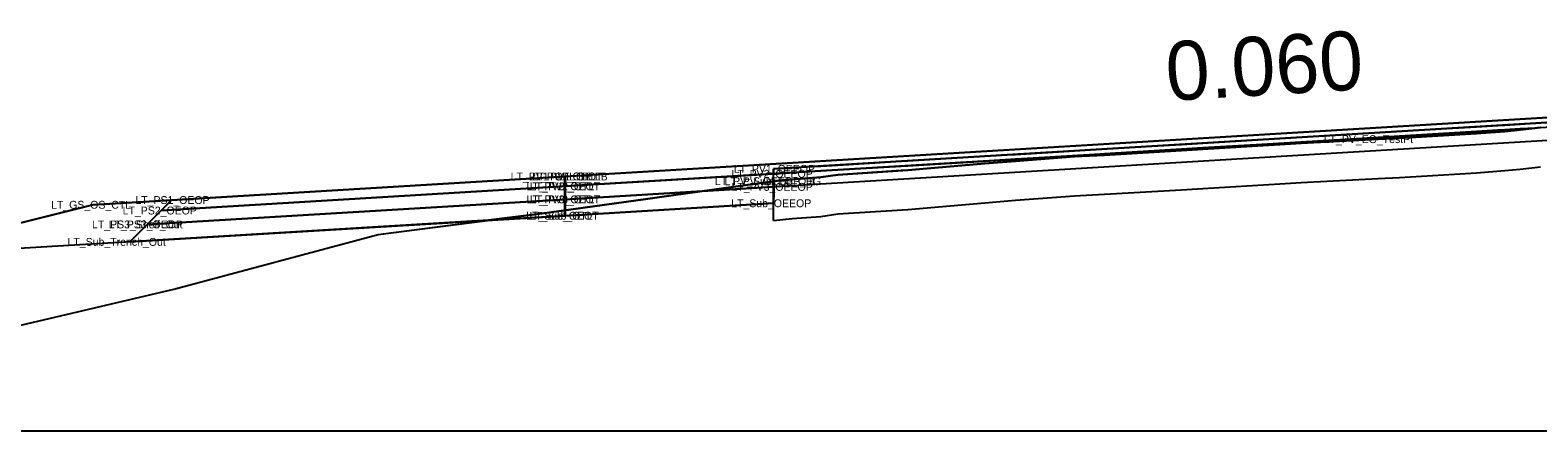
# Model space of a CAD drawing. Extents: x 2177029 to 2201446, y 59897 to 78390.
# Drawn here: x 2200163.13 to 2200201.47, y 66407.31 to 66417.51 of the extents above; entities that cross this region are included whole.
import ezdxf

# ---------------------------------------------------------------- set-up
doc = ezdxf.new("R2010")
doc.units = 0
for name, color, linetype in [('Exist Cross Section Cell', 7, 'Continuous'), ('Exist PHM Roadway Shape', 7, 'Continuous'), ('Exist XS Ground Line', 7, 'Continuous'), ('Old_Level_11', 7, 'Continuous'), ('Prop CMT Conc Surface', 7, 'Continuous'), ('Prop CMT Concrete Structures', 7, 'Continuous'), ('Prop CMT Guardrail Graphics', 7, 'Continuous'), ('Prop CMT Pvmt Course 1', 7, 'Continuous'), ('Prop CMT Pvmt Course 1 CG', 7, 'Continuous'), ('Prop CMT Pvmt Course 2', 7, 'Continuous'), ('Prop CMT Pvmt Course 2 CG', 7, 'Continuous'), ('Prop CMT Pvmt Course 3', 7, 'Continuous'), ('Prop CMT Pvmt Course 4', 7, 'Continuous'), ('Prop CMT Pvmt Surface', 7, 'Continuous'), ('Prop CMT Pvmt Wedge Surface 1', 7, 'Continuous'), ('Prop CMT Slope Grass', 7, 'Continuous'), ('Prop CMT Subgrade Earthwork', 7, 'Continuous'), ('Prop Hatching', 7, 'Continuous'), ('Prop XS Side Slope Text', 7, 'Continuous'), ('Scratch_Level_0', 7, 'Continuous'), ('Scratch_Level_9', 7, 'Continuous')]:
    doc.layers.add(name, color=color, linetype=linetype)

msp = doc.modelspace()

# ---------------------------------------------------------------- linework, layer by layer
at = {"layer": 'Exist Cross Section Cell'}
msp.add_line((2200042.732, 66407.31), (2200242.732, 66407.31), dxfattribs=at)
at = {"layer": 'Exist XS Ground Line'}
msp.add_lwpolyline([(2200157.174, 66408.66), (2200164.042, 66410.272), (2200166.779, 66410.917), (2200171.977, 66412.306), (2200176.077, 66412.833), (2200178.837, 66413.214), (2200179.489, 66413.304), (2200182.033, 66413.663), (2200182.506, 66413.71), (2200183.234, 66413.763), (2200183.666, 66413.829), (2200185.452, 66413.945), (2200187.41, 66414.111), (2200188.183, 66414.177), (2200189.689, 66414.293), (2200190.452, 66414.329), (2200192.41, 66414.442), (2200192.952, 66414.475), (2200194.909, 66414.6), (2200195.452, 66414.634), (2200197.408, 66414.734), (2200197.952, 66414.761), (2200199.908, 66414.88), (2200200.627, 66414.932), (2200201.019, 66414.972), (2200201.537, 66415.03)], dxfattribs=at)
at = {"layer": 'Prop CMT Conc Surface'}
for points in [[(2200212.732, 66415.819), (2200182.033, 66413.977)], [(2200182.033, 66413.977), (2200182.033, 66413.852)], [(2200182.033, 66413.852), (2200176.732, 66413.534)], [(2200176.732, 66413.534), (2200176.732, 66413.784)]]:
    msp.add_lwpolyline(points, dxfattribs=at)
at = {"layer": 'Prop CMT Concrete Structures'}
for p, q in [((2200212.732, 66415.944), (2200176.732, 66413.784)), ((2200176.732, 66413.784), (2200176.722, 66413.783))]:
    msp.add_line(p, q, dxfattribs=at)
at = {"layer": 'Prop CMT Guardrail Graphics'}
for points in [[(2200212.732, 66415.36), (2200176.732, 66413.201)], [(2200176.732, 66413.201), (2200176.732, 66413.784)]]:
    msp.add_lwpolyline(points, dxfattribs=at)
at = {"layer": 'Prop CMT Pvmt Course 1'}
for points in [[(2200182.033, 66413.852), (2200182.333, 66413.87), (2200182.506, 66413.881), (2200182.838, 66413.901), (2200182.952, 66413.908), (2200183.234, 66413.924), (2200183.666, 66413.95), (2200185.275, 66414.047), (2200185.452, 66414.058), (2200187.41, 66414.175), (2200187.952, 66414.208), (2200188.183, 66414.221), (2200189.689, 66414.312), (2200190.355, 66414.352), (2200190.452, 66414.358), (2200192.41, 66414.475), (2200192.952, 66414.508), (2200194.909, 66414.625), (2200195.452, 66414.658), (2200197.408, 66414.775), (2200197.952, 66414.808), (2200199.908, 66414.925), (2200200.453, 66414.958), (2200200.627, 66414.968), (2200201.019, 66414.992), (2200201.402, 66415.015)], [(2200201.402, 66415.015), (2200201.019, 66414.972), (2200200.627, 66414.932), (2200200.453, 66414.914), (2200199.908, 66414.88), (2200197.952, 66414.761), (2200197.408, 66414.734), (2200195.452, 66414.634), (2200194.909, 66414.6), (2200192.952, 66414.475), (2200192.41, 66414.442), (2200190.452, 66414.329), (2200190.355, 66414.325), (2200189.689, 66414.293), (2200188.183, 66414.177), (2200187.952, 66414.158), (2200187.41, 66414.111), (2200185.452, 66413.945), (2200185.275, 66413.934), (2200183.666, 66413.829), (2200183.234, 66413.763), (2200182.952, 66413.734), (2200182.838, 66413.728), (2200182.506, 66413.71), (2200182.333, 66413.694), (2200182.033, 66413.663)], [(2200182.033, 66413.663), (2200182.033, 66413.852)]]:
    msp.add_lwpolyline(points, dxfattribs=at)
at = {"layer": 'Prop CMT Pvmt Course 1 CG'}
for points in [[(2200176.722, 66413.2), (2200166.101, 66412.563)], [(2200176.722, 66412.783), (2200176.722, 66413.2)], [(2200165.659, 66412.119), (2200176.722, 66412.783)], [(2200166.101, 66412.563), (2200165.659, 66412.119)], [(2200166.101, 66412.563), (2200166.101, 66412.563)]]:
    msp.add_lwpolyline(points, dxfattribs=at)
at = {"layer": 'Prop CMT Pvmt Course 2'}
for points in [[(2200176.732, 66413.201), (2200176.722, 66413.2)], [(2200176.722, 66413.2), (2200176.722, 66412.783)], [(2200182.033, 66413.519), (2200176.732, 66413.201)], [(2200176.732, 66412.784), (2200176.732, 66413.201)], [(2200176.732, 66413.201), (2200176.732, 66412.784)], [(2200182.033, 66413.102), (2200182.033, 66413.519)], [(2200176.732, 66412.784), (2200182.033, 66413.102)], [(2200176.722, 66412.783), (2200176.732, 66412.784)]]:
    msp.add_lwpolyline(points, dxfattribs=at)
at = {"layer": 'Prop CMT Pvmt Course 2 CG'}
for points in [[(2200212.732, 66415.944), (2200176.732, 66413.784)], [(2200182.033, 66413.977), (2200212.732, 66415.819)], [(2200182.033, 66413.852), (2200182.033, 66413.977)], [(2200176.732, 66413.784), (2200176.724, 66413.783), (2200176.722, 66413.783)], [(2200176.722, 66413.783), (2200176.722, 66413.533)], [(2200176.732, 66413.534), (2200182.033, 66413.852)], [(2200176.732, 66413.534), (2200176.732, 66413.784)], [(2200176.732, 66413.784), (2200176.732, 66413.534)], [(2200176.722, 66413.533), (2200176.732, 66413.534)]]:
    msp.add_lwpolyline(points, dxfattribs=at)
at = {"layer": 'Prop CMT Pvmt Course 3'}
for points in [[(2200182.033, 66413.102), (2200182.048, 66413.664)], [(2200182.033, 66413.102), (2200176.732, 66412.784)], [(2200176.722, 66412.783), (2200165.659, 66412.119)], [(2200176.732, 66412.784), (2200176.722, 66412.783)], [(2200165.659, 66412.119), (2200159.458, 66411.747)]]:
    msp.add_lwpolyline(points, dxfattribs=at)
at = {"layer": 'Prop CMT Pvmt Course 4'}
msp.add_lwpolyline([(2200176.722, 66413.783), (2200166.723, 66413.183)], dxfattribs=at)
at = {"layer": 'Prop CMT Pvmt Surface'}
for points in [[(2200182.033, 66413.977), (2200182.333, 66413.995), (2200182.506, 66414.006), (2200182.838, 66414.026), (2200182.952, 66414.033), (2200183.234, 66414.049), (2200183.666, 66414.075), (2200185.275, 66414.172), (2200185.452, 66414.183), (2200187.41, 66414.3), (2200187.952, 66414.333), (2200188.183, 66414.346), (2200189.689, 66414.437), (2200190.355, 66414.477), (2200190.452, 66414.483), (2200192.41, 66414.6), (2200192.952, 66414.633), (2200194.909, 66414.75), (2200195.452, 66414.783), (2200197.408, 66414.9), (2200197.952, 66414.933), (2200199.908, 66415.05), (2200200.453, 66415.083), (2200200.627, 66415.093), (2200201.019, 66415.117), (2200201.537, 66415.148)], [(2200201.537, 66415.03), (2200201.402, 66415.015), (2200201.019, 66414.992), (2200200.627, 66414.968), (2200200.453, 66414.958), (2200199.908, 66414.925), (2200197.952, 66414.808), (2200197.408, 66414.775), (2200195.452, 66414.658), (2200194.909, 66414.625), (2200192.952, 66414.508), (2200192.41, 66414.475), (2200190.452, 66414.358), (2200190.355, 66414.352), (2200189.689, 66414.312), (2200188.183, 66414.221), (2200187.952, 66414.208), (2200187.41, 66414.175), (2200185.452, 66414.058), (2200185.275, 66414.047), (2200183.666, 66413.95), (2200183.234, 66413.924), (2200182.952, 66413.908), (2200182.838, 66413.901), (2200182.506, 66413.881), (2200182.333, 66413.87), (2200182.033, 66413.852)], [(2200182.033, 66413.852), (2200182.033, 66413.977)]]:
    msp.add_lwpolyline(points, dxfattribs=at)
at = {"layer": 'Prop CMT Pvmt Wedge Surface 1'}
for p, q in [((2200200.627, 66413.932), (2200201.019, 66413.972)), ((2200201.019, 66413.972), (2200201.537, 66414.03)), ((2200182.033, 66412.663), (2200182.033, 66413.663)), ((2200192.952, 66413.475), (2200194.909, 66413.6)), ((2200194.909, 66413.6), (2200195.452, 66413.634)), ((2200195.452, 66413.634), (2200197.408, 66413.734)), ((2200197.408, 66413.734), (2200197.952, 66413.761)), ((2200197.952, 66413.761), (2200199.908, 66413.88)), ((2200199.908, 66413.88), (2200200.627, 66413.932)), ((2200187.41, 66413.111), (2200188.183, 66413.177)), ((2200188.183, 66413.177), (2200189.689, 66413.293)), ((2200189.689, 66413.293), (2200190.452, 66413.329)), ((2200190.452, 66413.329), (2200192.41, 66413.442)), ((2200192.41, 66413.442), (2200192.952, 66413.475)), ((2200183.234, 66412.763), (2200183.666, 66412.829)), ((2200183.666, 66412.829), (2200185.452, 66412.945)), ((2200185.452, 66412.945), (2200187.41, 66413.111)), ((2200182.033, 66412.663), (2200182.506, 66412.71)), ((2200182.506, 66412.71), (2200183.234, 66412.763))]:
    msp.add_line(p, q, dxfattribs=at)
at = {"layer": 'Prop CMT Slope Grass'}
for points in [[(2200182.033, 66413.852), (2200176.732, 66413.534)], [(2200182.033, 66413.519), (2200182.033, 66413.852)], [(2200176.732, 66413.534), (2200176.722, 66413.533)], [(2200176.722, 66413.533), (2200176.722, 66413.2)], [(2200176.722, 66413.2), (2200176.732, 66413.201)], [(2200176.732, 66413.201), (2200176.732, 66413.534)], [(2200176.732, 66413.534), (2200176.732, 66413.201)], [(2200176.732, 66413.201), (2200182.033, 66413.519)]]:
    msp.add_lwpolyline(points, dxfattribs=at)
at = {"layer": 'Prop CMT Subgrade Earthwork'}
for points in [[(2200212.732, 66415.694), (2200176.732, 66413.534)], [(2200176.732, 66413.534), (2200176.732, 66413.784)]]:
    msp.add_lwpolyline(points, dxfattribs=at)
at = {"layer": 'Prop Hatching'}
msp.add_lwpolyline([(2200166.723, 66413.183), (2200164.722, 66413.063), (2200143.91, 66407.86)], dxfattribs=at)
at = {"layer": 'Prop XS Side Slope Text'}
msp.add_lwpolyline([(2200201.537, 66415.03), (2200201.019, 66414.972), (2200200.627, 66414.932), (2200199.908, 66414.88), (2200197.952, 66414.761), (2200197.408, 66414.734), (2200195.452, 66414.634), (2200194.909, 66414.6), (2200192.952, 66414.475), (2200192.41, 66414.442), (2200190.452, 66414.329), (2200189.689, 66414.293), (2200188.183, 66414.177), (2200187.41, 66414.111), (2200185.452, 66413.945), (2200183.666, 66413.829), (2200183.234, 66413.763), (2200182.506, 66413.71), (2200182.048, 66413.664), (2200179.489, 66413.304), (2200178.837, 66413.214), (2200176.077, 66412.833), (2200174.787, 66412.668), (2200165.659, 66412.119), (2200159.457, 66411.747), (2200164.722, 66413.063), (2200166.723, 66413.183), (2200176.722, 66413.783), (2200212.732, 66415.944)], dxfattribs=at)
for points in [[(2200182.033, 66413.102), (2200176.732, 66412.784), (2200174.787, 66412.668), (2200176.077, 66412.833), (2200178.837, 66413.214), (2200179.489, 66413.304), (2200182.048, 66413.664)], [(2200165.659, 66412.119), (2200159.457, 66411.747), (2200148.792, 66409.081), (2200148.893, 66409.078), (2200157.174, 66408.66), (2200164.042, 66410.272), (2200166.779, 66410.917), (2200171.977, 66412.306), (2200174.787, 66412.668)]]:
    msp.add_lwpolyline(points, close=True, dxfattribs=at)
at = {"layer": 'Scratch_Level_0'}
for points in [[(2200176.722, 66413.533), (2200166.456, 66412.917), (2200166.101, 66412.563)], [(2200166.101, 66412.563), (2200176.722, 66413.2)], [(2200176.722, 66413.2), (2200176.722, 66413.533)]]:
    msp.add_lwpolyline(points, dxfattribs=at)
at = {"layer": 'Scratch_Level_9'}
for points in [[(2200176.722, 66413.783), (2200166.723, 66413.183), (2200166.456, 66412.917)], [(2200176.722, 66413.533), (2200176.722, 66413.783)], [(2200166.456, 66412.917), (2200176.722, 66413.533)]]:
    msp.add_lwpolyline(points, dxfattribs=at)

# ---------------------------------------------------------------- texts
at = {"layer": 'Exist PHM Roadway Shape'}
for s, p in [('LT_PV_EG_TestPt', (2200196.024, 66414.633)), ('LT_PV2_OEEOP', (2200180.964, 66413.752)), ('LT_PV1_OEEOP', (2200181.021, 66413.877)), ('LT_PV1_OTL SE LB', (2200175.347, 66413.683)), ('LT_PV2_OEOT', (2200175.749, 66413.434)), ('LT_PV1_OEOT', (2200175.806, 66413.684)), ('LT_PV2_OTL', (2200175.837, 66413.433)), ('LT_PV1_OTL', (2200175.894, 66413.683)), ('LT_PV_Sub_Tie_Out', (2200180.543, 66413.564)), ('LT_PV_OEEOP_EG', (2200180.788, 66413.562)), ('LT_PV3_OEEOP', (2200180.964, 66413.419)), ('LT_PS1_OEOP', (2200165.803, 66413.083)), ('LT_PV3_OEOT', (2200175.749, 66413.101)), ('LT_PV3_OTL', (2200175.837, 66413.1)), ('LT_Sub_OEEOP', (2200180.955, 66413.002)), ('LT_GS_OS_CTL', (2200163.659, 66412.963)), ('LT_PS2_OEOP', (2200165.48, 66412.817)), ('LT_Sub_OEOT', (2200175.74, 66412.684)), ('LT_Sub_OTL', (2200175.828, 66412.683)), ('LT_PS3_Shelf_Out', (2200164.7, 66412.463)), ('LT_PS3_OEOP', (2200165.125, 66412.463)), ('LT_Sub_Trench_Out', (2200164.079, 66412.019))]:
    msp.add_text(s, height=0.2, dxfattribs=at).set_placement(p)
at = {"layer": 'Old_Level_11'}
msp.add_text('0.060', height=1.5, rotation=3.4336, dxfattribs=at).set_placement((2200192.052, 66415.705))

doc.saveas('drawing.dxf')
